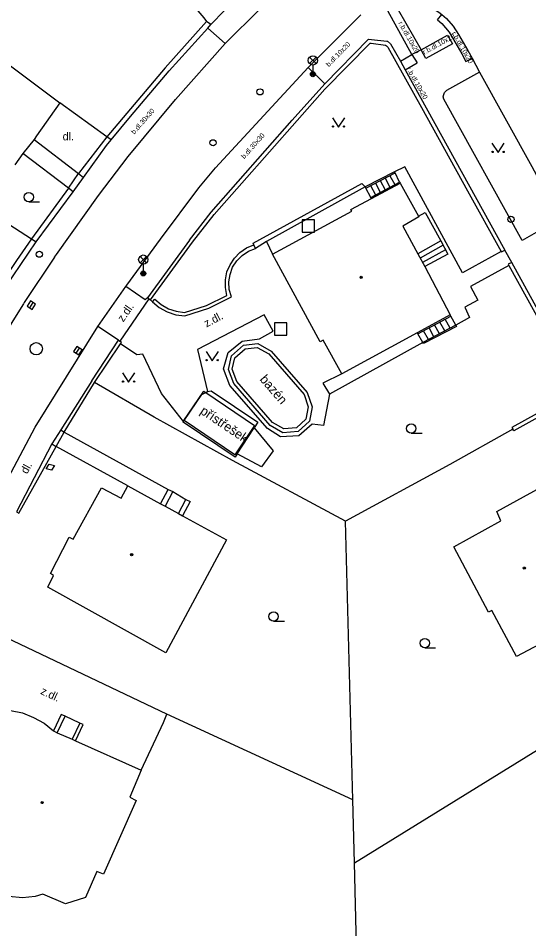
# Model space of a CAD drawing. Extents: x -600309 to -598967, y -1161267 to -1160292.
# Drawn here: x -599938 to -599896.6, y -1160562.7 to -1160488.8 of the extents above; entities that cross this region are included whole.
import ezdxf

# ---------------------------------------------------------------- set-up
doc = ezdxf.new("R2010")
doc.units = 0
for name, color, linetype in [('Level 10', 7, 'Continuous'), ('Level 11', 7, 'Continuous'), ('Level 24', 7, 'Continuous'), ('Level 26', 7, 'Continuous'), ('Level 27', 7, 'Continuous'), ('Level 28', 7, 'Continuous'), ('Level 31', 7, 'Continuous'), ('Level 33', 7, 'Continuous'), ('Level 36', 7, 'Continuous'), ('Level 39', 7, 'Continuous'), ('Level 40', 7, 'Continuous'), ('Level 42', 7, 'Continuous'), ('Level 5', 7, 'Continuous'), ('Level 51', 7, 'Continuous'), ('Level 6', 7, 'Continuous'), ('Level 7', 7, 'Continuous'), ('Level 8', 7, 'Continuous')]:
    doc.layers.add(name, color=color, linetype=linetype)

msp = doc.modelspace()

# ---------------------------------------------------------------- linework, layer by layer
at = {"layer": 'Level 10'}
for points in [[(-599935.03, -1160508.16), (-599934.89, -1160507.96), (-599931.48, -1160503.15), (-599929.06, -1160499.99), (-599925.22, -1160495.36), (-599921.2, -1160490.82), (-599918.35, -1160488), (-599916.19, -1160485.82), (-599913.18, -1160482.88), (-599912.64, -1160482.36)], [(-599904.54, -1160487.84), (-599903.85, -1160488.27), (-599903.61, -1160488.47), (-599903.24, -1160488.79), (-599902.7, -1160489.4), (-599902.26, -1160490.08)], [(-599929.17, -1160510.45), (-599926.44, -1160506.7), (-599923.32, -1160502.53), (-599921.97, -1160500.92), (-599914.47, -1160492.76), (-599913.88, -1160492.17), (-599910.18, -1160488.49)], [(-599902.26, -1160490.08), (-599901.51, -1160491.38), (-599901.17, -1160492.01), (-599900.56, -1160493.13)], [(-599900.56, -1160493.13), (-599896.33, -1160500.81), (-599894.52, -1160504.12)], [(-599935.03, -1160508.16), (-599937.49, -1160511.84), (-599937.56, -1160511.95), (-599938.03, -1160512.7), (-599939.64, -1160515.26), (-599941.75, -1160518.63), (-599946.15, -1160526.95), (-599959.57, -1160556.4699), (-599964.29, -1160566.81), (-599966.33, -1160571.27), (-599969.39, -1160577.98), (-599972.6, -1160585.01), (-599977.2, -1160595.1)], [(-599931.52, -1160513.79), (-599929.25, -1160510.56), (-599929.17, -1160510.45)], [(-599971.83, -1160598.12), (-599968.08, -1160589.86), (-599959.85, -1160571.72), (-599958.48, -1160568.71), (-599957.16, -1160565.81), (-599954.26, -1160559.42), (-599946.03, -1160541.39), (-599945.51, -1160540.25), (-599944.42, -1160537.85), (-599944.31, -1160537.6), (-599940.51, -1160529.28), (-599936.62, -1160521.9699), (-599931.52, -1160513.79)]]:
    msp.add_lwpolyline(points, dxfattribs=at)
at = {"layer": 'Level 11'}
for points in [[(-599925.56, -1160485.64), (-599922.94, -1160488.74), (-599922.7, -1160489.03)], [(-599907.16, -1160488.08), (-599905.3, -1160491.34), (-599906.04, -1160491.72), (-599908, -1160488.16)], [(-599922.36, -1160489.28), (-599922.7, -1160489.03)], [(-599903.96, -1160488.9), (-599903.61, -1160488.47)], [(-599903.96, -1160488.9), (-599903.62, -1160489.2), (-599903.31, -1160489.53), (-599903.03, -1160489.89)], [(-599922.59, -1160489.57), (-599921.2, -1160490.82)], [(-599903.03, -1160489.89), (-599902.75, -1160490.36), (-599902, -1160491.65), (-599901.66, -1160492.28)], [(-599902.75, -1160490.83), (-599904.91, -1160492.03), (-599905.3, -1160491.34), (-599903.15, -1160490.15)], [(-599903.15, -1160490.15), (-599902.75, -1160490.83)], [(-599906.97, -1160492.25), (-599906.04, -1160491.72)], [(-599906.04, -1160491.72), (-599905.61, -1160492.38)], [(-599901.66, -1160492.28), (-599901.17, -1160492.01)], [(-599914.47, -1160492.76), (-599913.1, -1160494.09)], [(-599906.59, -1160492.94), (-599905.61, -1160492.38)], [(-599900.56, -1160493.13), (-599903.25, -1160494.64)], [(-599903.46, -1160495.34), (-599903.5, -1160495.15), (-599903.47, -1160494.95), (-599903.39, -1160494.78), (-599903.25, -1160494.64)], [(-599895.97, -1160506.17), (-599897.09, -1160506.81), (-599903.46, -1160495.34)], [(-599936.7, -1160498.62), (-599933.09, -1160501.36)], [(-599933.92, -1160502.56), (-599937.61, -1160499.76)], [(-599898.8, -1160507.71), (-599901.93, -1160509.45), (-599906.62, -1160500.82), (-599907.45, -1160501.23)], [(-599933.92, -1160502.56), (-599933.09, -1160501.36)], [(-599907.45, -1160501.23), (-599909.83, -1160502.46)], [(-599909.78, -1160502.55), (-599907.4, -1160501.32)], [(-599908.23, -1160501.75), (-599907.83, -1160502.48)], [(-599907.84, -1160501.55), (-599907.44, -1160502.27)], [(-599907.4, -1160501.32), (-599907.45, -1160501.23)], [(-599907.06, -1160502.07), (-599907.4, -1160501.32)], [(-599918.86, -1160507.1599), (-599918.93, -1160507.02), (-599910.11, -1160502.18), (-599909.83, -1160502.46)], [(-599909.83, -1160502.46), (-599917.84, -1160506.9)], [(-599909.83, -1160502.46), (-599909.78, -1160502.55)], [(-599909.4, -1160502.35), (-599909, -1160503.11)], [(-599909.38, -1160503.31), (-599907.06, -1160502.07)], [(-599909.01, -1160502.15), (-599908.61, -1160502.9)], [(-599908.62, -1160501.95), (-599908.2199, -1160502.69)], [(-599907.06, -1160502.07), (-599907.01, -1160502.1599)], [(-599909.38, -1160503.31), (-599909.78, -1160502.55)], [(-599909.33, -1160503.4), (-599909.38, -1160503.31)], [(-599905.51, -1160504.85), (-599904.98, -1160504.55), (-599903.69, -1160506.85)], [(-599917.84, -1160506.9), (-599918.73, -1160507.45)], [(-599917.84, -1160506.9), (-599917.35, -1160507.9099)], [(-599903.69, -1160506.85), (-599905.56, -1160507.89)], [(-599903.69, -1160506.85), (-599903.13, -1160507.9099), (-599905.01, -1160508.93)], [(-599921.05, -1160511.27), (-599921.17, -1160510.64), (-599921.17, -1160510), (-599921.05, -1160509.37), (-599920.8, -1160508.78), (-599920.45, -1160508.24), (-599920, -1160507.78), (-599919.4699, -1160507.42), (-599918.86, -1160507.1599)], [(-599920.69, -1160511.4), (-599920.86, -1160510.8), (-599920.89, -1160510.18), (-599920.8, -1160509.57), (-599920.59, -1160508.99), (-599920.26, -1160508.4699), (-599919.82, -1160508.02), (-599919.31, -1160507.68), (-599918.73, -1160507.45)], [(-599918.73, -1160507.45), (-599918.86, -1160507.1599)], [(-599903.5, -1160507.2), (-599905.37, -1160508.24)], [(-599903.32, -1160507.56), (-599905.18, -1160508.6)], [(-599898.19, -1160508.83), (-599901.29, -1160510.56), (-599900.71, -1160511.6599), (-599901.75, -1160512.24), (-599901.38, -1160513.08), (-599902.49, -1160513.7)], [(-599927.5, -1160511.46), (-599927.69, -1160511.64), (-599929.25, -1160510.56)], [(-599926.89, -1160511.58), (-599926.38, -1160512.02), (-599925.79, -1160512.35), (-599925.1599, -1160512.56), (-599924.49, -1160512.65), (-599922.7199, -1160512.08), (-599921.05, -1160511.27)], [(-599927.1, -1160511.79), (-599927.25, -1160511.63)], [(-599927.1, -1160511.79), (-599926.54, -1160512.26), (-599925.89, -1160512.62), (-599925.19, -1160512.85), (-599924.46, -1160512.94), (-599922.52, -1160512.31), (-599920.69, -1160511.4)], [(-599927.1, -1160511.79), (-599926.89, -1160511.58)], [(-599912.7199, -1160519.28), (-599913.23, -1160521.85), (-599914.13, -1160521.74), (-599915.21, -1160522.69), (-599916.7199, -1160522.77), (-599917.77, -1160522.09), (-599920.81, -1160518.6), (-599921.34, -1160517.23), (-599920.95, -1160515.9), (-599919.83, -1160514.99), (-599918.4099, -1160514.8), (-599917.31, -1160514.19), (-599918.02, -1160512.84), (-599923.43, -1160515.6599), (-599922.62, -1160519.09)], [(-599902.9, -1160512.96), (-599902.95, -1160512.86)], [(-599905.56, -1160514.4), (-599902.9, -1160512.96)], [(-599903.37, -1160514.1599), (-599903.78, -1160513.44)], [(-599902.93, -1160513.93), (-599903.34, -1160513.2)], [(-599902.49, -1160513.7), (-599902.9, -1160512.96)], [(-599929.85, -1160514.92), (-599931.52, -1160513.79)], [(-599905.61, -1160514.31), (-599905.56, -1160514.4)], [(-599902.49, -1160513.7), (-599905.1599, -1160515.1)], [(-599902.49, -1160513.7), (-599902.44, -1160513.79), (-599905.11, -1160515.19), (-599905.1599, -1160515.1)], [(-599904.7, -1160514.86), (-599905.1, -1160514.15)], [(-599904.26, -1160514.63), (-599904.6599, -1160513.9099)], [(-599903.81, -1160514.39), (-599904.2199, -1160513.67)], [(-599905.1599, -1160515.1), (-599905.56, -1160514.4)], [(-599924.57, -1160521.51), (-599926.36, -1160519.25), (-599927.88, -1160516.05), (-599928.35, -1160516.09), (-599929.68, -1160515.21)], [(-599917.46, -1160515.79), (-599914.54, -1160519.1599), (-599914.14, -1160520.31), (-599914.36, -1160521.48), (-599915.27, -1160522.32), (-599916.51, -1160522.42), (-599917.54, -1160521.84), (-599920.5, -1160518.42), (-599920.93, -1160517.3), (-599920.69, -1160516.17), (-599919.71, -1160515.31), (-599918.54, -1160515.18), (-599917.46, -1160515.79)], [(-599917.65, -1160516.03), (-599914.8, -1160519.31), (-599914.45, -1160520.33), (-599914.64, -1160521.33), (-599915.4, -1160522.03), (-599916.44, -1160522.11), (-599917.35, -1160521.6), (-599920.24, -1160518.26), (-599920.62, -1160517.27), (-599920.42, -1160516.33), (-599919.58, -1160515.6), (-599918.6, -1160515.49), (-599917.65, -1160516.03)], [(-599905.1599, -1160515.1), (-599912.7199, -1160519.28)], [(-599911.74, -1160517.63), (-599913.27, -1160518.39), (-599912.7199, -1160519.28)], [(-599924.53, -1160521.44), (-599923.09, -1160519.32), (-599922.76, -1160519.1599)], [(-599922.76, -1160519.1599), (-599922.62, -1160519.09)], [(-599922.62, -1160519.09), (-599922.34, -1160519.01), (-599918.55, -1160521.56), (-599918.84, -1160522.03)], [(-599920.21, -1160524.13), (-599920.38, -1160524.4099), (-599924.61, -1160521.57), (-599924.57, -1160521.51)], [(-599924.57, -1160521.51), (-599924.53, -1160521.44)], [(-599934.92, -1160523.54), (-599934.26, -1160522.37)], [(-599934.26, -1160522.37), (-599925.83, -1160527.03)], [(-599918.84, -1160522.03), (-599917.29, -1160523.9), (-599918.26, -1160525.2), (-599920.21, -1160524.13)], [(-599920.21, -1160524.13), (-599918.84, -1160522.03)], [(-599929.1, -1160526.74), (-599934.92, -1160523.54)], [(-599926.43, -1160528.2), (-599925.83, -1160527.03)], [(-599925.45, -1160527.21), (-599926.06, -1160528.4)], [(-599925.83, -1160527.03), (-599925.45, -1160527.21)], [(-599925.45, -1160527.21), (-599924.38, -1160527.84)], [(-599924.98, -1160528.99), (-599924.38, -1160527.84)], [(-599924.04, -1160528), (-599924.6599, -1160529.17)], [(-599924.38, -1160527.84), (-599924.04, -1160528)], [(-599934.19, -1160545.45), (-599934.51, -1160545.3), (-599935.13, -1160546.64)], [(-599926.2, -1160545.9699), (-599925.94, -1160545.28)], [(-599934.83, -1160546.79), (-599934.19, -1160545.45)], [(-599933, -1160546), (-599934.19, -1160545.45)], [(-599933, -1160546), (-599933.6, -1160547.32)], [(-599933.34, -1160547.46), (-599932.73, -1160546.12), (-599933, -1160546)], [(-599928.01, -1160549.84), (-599926.2, -1160545.9699)]]:
    msp.add_lwpolyline(points, dxfattribs=at)
at = {"layer": 'Level 24'}
msp.add_lwpolyline([(-599935.72, -1160525.35), (-599935.47, -1160524.97), (-599935.04, -1160525.09), (-599935.29, -1160525.47), (-599935.72, -1160525.35)], dxfattribs=at)
at = {"layer": 'Level 26'}
for points in [[(-599914.94, -1160506.14), (-599913.94, -1160506.14), (-599913.94, -1160505.14), (-599914.94, -1160505.14)], [(-599917.2, -1160514.49), (-599916.2, -1160514.49), (-599916.2, -1160513.49), (-599917.2, -1160513.49)]]:
    msp.add_lwpolyline(points, close=True, dxfattribs=at)
at = {"layer": 'Level 27'}
for p, q in [((-599937.054, -1160512.281), (-599936.786, -1160511.859)), ((-599933.2867, -1160515.9693), (-599933.0133, -1160515.5507))]:
    msp.add_line(p, q, dxfattribs=at)
for points in [[(-599936.843, -1160512.4151), (-599936.5749, -1160511.993), (-599936.997, -1160511.7249), (-599937.2651, -1160512.147)], [(-599933.0773, -1160516.106), (-599932.804, -1160515.6873), (-599933.2227, -1160515.414), (-599933.496, -1160515.8327)]]:
    msp.add_lwpolyline(points, close=True, dxfattribs=at)
msp.add_circle((-599936.52, -1160515.6), 0.5, dxfattribs=at)
at = {"layer": 'Level 28'}
for centre in [(-599918.37, -1160494.74), (-599922.18, -1160498.88), (-599936.27, -1160507.93)]:
    msp.add_circle(centre, 0.25, dxfattribs=at)
at = {"layer": 'Level 31'}
msp.add_circle((-599898.01, -1160505.1), 0.25, dxfattribs=at)
at = {"layer": 'Level 33'}
for p, q in [((-599914.345, -1160492.45), (-599913.815, -1160491.92)), ((-599914.345, -1160491.92), (-599913.815, -1160492.45)), ((-599914.08, -1160492.56), (-599914.08, -1160493.31)), ((-599928.105, -1160508.63), (-599927.575, -1160508.1)), ((-599928.105, -1160508.1), (-599927.575, -1160508.63)), ((-599927.84, -1160508.74), (-599927.84, -1160509.49))]:
    msp.add_line(p, q, dxfattribs=at)
for centre, radius in [((-599914.08, -1160492.185), 0.375), ((-599914.08, -1160493.31), 0.2), ((-599914.08, -1160493.31), 0.1445), ((-599914.08, -1160493.31), 0.0876), ((-599927.84, -1160508.365), 0.375), ((-599927.84, -1160509.49), 0.2), ((-599927.84, -1160509.49), 0.1445), ((-599927.84, -1160509.49), 0.0876)]:
    msp.add_circle(centre, radius, dxfattribs=at)
at = {"layer": 'Level 36'}
for p, q in [((-599937.13, -1160503.665), (-599936.255, -1160503.665)), ((-599906.1, -1160522.455), (-599905.225, -1160522.455)), ((-599917.27, -1160537.725), (-599916.395, -1160537.725)), ((-599905, -1160539.885), (-599904.125, -1160539.885))]:
    msp.add_line(p, q, dxfattribs=at)
for points in [[(-599912.5, -1160496.85), (-599912, -1160497.6), (-599911.5, -1160496.85)], [(-599899.55, -1160498.92), (-599899.05, -1160499.67), (-599898.55, -1160498.92)], [(-599922.75, -1160515.83), (-599922.25, -1160516.58), (-599921.75, -1160515.83)], [(-599929.53, -1160517.57), (-599929.03, -1160518.32), (-599928.53, -1160517.57)]]:
    msp.add_lwpolyline(points, dxfattribs=at)
for centre, radius in [((-599912.4502, -1160497.5498), 0.05), ((-599911.5508, -1160497.5498), 0.05), ((-599899.5002, -1160499.6198), 0.05), ((-599898.6008, -1160499.6198), 0.05), ((-599937.1301, -1160503.2899), 0.375), ((-599922.7002, -1160516.5298), 0.05), ((-599921.8008, -1160516.5298), 0.05), ((-599929.4802, -1160518.2698), 0.05), ((-599928.5808, -1160518.2698), 0.05), ((-599906.1001, -1160522.0799), 0.375), ((-599917.2701, -1160537.3499), 0.375), ((-599905.0001, -1160539.5099), 0.375)]:
    msp.add_circle(centre, radius, dxfattribs=at)
at = {"layer": 'Level 39'}
for centre, radius in [((-599910.1599, -1160509.8), 0.09), ((-599910.1599, -1160509.8), 0.0398), ((-599928.79, -1160532.33), 0.09), ((-599928.79, -1160532.33), 0.0398), ((-599896.93, -1160533.42), 0.09), ((-599896.93, -1160533.42), 0.0398), ((-599936.04, -1160552.46), 0.09), ((-599936.04, -1160552.46), 0.0398)]:
    msp.add_circle(centre, radius, dxfattribs=at)
at = {"layer": 'Level 5'}
for points in [[(-599943.04, -1160489.33), (-599934.62, -1160495.63)], [(-599934.62, -1160495.63), (-599936.51, -1160498.3)], [(-599936.7, -1160498.62), (-599937.61, -1160499.76)], [(-599936.51, -1160498.3), (-599936.7, -1160498.62)], [(-599937.61, -1160499.76), (-599938.27, -1160500.67)], [(-599909.33, -1160503.4), (-599907.01, -1160502.1599)], [(-599907.01, -1160502.1599), (-599905.51, -1160504.85)], [(-599911, -1160504.29), (-599909.33, -1160503.4)], [(-599917.35, -1160507.9099), (-599910.92, -1160504.44)], [(-599910.92, -1160504.44), (-599911, -1160504.29)], [(-599905.48, -1160504.9), (-599906.78, -1160505.64)], [(-599905.51, -1160504.85), (-599905.48, -1160504.9)], [(-599906.78, -1160505.64), (-599905.56, -1160507.89)], [(-599913.5, -1160515.05), (-599917.35, -1160507.9099)], [(-599905.56, -1160507.89), (-599905.01, -1160508.93)], [(-599905.01, -1160508.93), (-599902.95, -1160512.86)], [(-599902.95, -1160512.86), (-599905.61, -1160514.31)], [(-599905.61, -1160514.31), (-599911.74, -1160517.63)], [(-599913.24, -1160514.9099), (-599913.5, -1160515.05)], [(-599911.74, -1160517.63), (-599913.24, -1160514.9099)], [(-599899.17, -1160528.81), (-599893.99, -1160525.99)], [(-599933.54, -1160531.06), (-599931.24, -1160526.9)], [(-599931.24, -1160526.9), (-599929.63, -1160527.73)], [(-599929.63, -1160527.73), (-599929.1, -1160526.74)], [(-599929.1, -1160526.74), (-599926.43, -1160528.2)], [(-599926.43, -1160528.2), (-599926.06, -1160528.4)], [(-599926.06, -1160528.4), (-599924.98, -1160528.99)], [(-599924.98, -1160528.99), (-599924.6599, -1160529.17)], [(-599898.84, -1160529.57), (-599899.17, -1160528.81)], [(-599924.6599, -1160529.17), (-599921.09, -1160531.13)], [(-599902.65, -1160531.7), (-599898.84, -1160529.57)], [(-599935.38, -1160533.86), (-599933.86, -1160530.92)], [(-599933.86, -1160530.92), (-599933.54, -1160531.06)], [(-599921.09, -1160531.13), (-599926.02, -1160540.29)], [(-599899.84, -1160537.01), (-599902.65, -1160531.7)], [(-599935.59, -1160534.98), (-599935.13, -1160534.01)], [(-599935.13, -1160534.01), (-599935.38, -1160533.86)], [(-599926.02, -1160540.29), (-599935.59, -1160534.98)], [(-599899.56, -1160536.85), (-599899.84, -1160537.01)], [(-599897.57, -1160540.6), (-599899.56, -1160536.85)], [(-599890.2199, -1160536.71), (-599897.57, -1160540.6)], [(-599938.61, -1160544.98), (-599937.65, -1160545.18)], [(-599937.65, -1160545.18), (-599936.74, -1160545.54)], [(-599936.74, -1160545.54), (-599935.89, -1160546.02)], [(-599935.89, -1160546.02), (-599935.13, -1160546.64)], [(-599935.13, -1160546.64), (-599934.83, -1160546.79)], [(-599934.83, -1160546.79), (-599933.6, -1160547.32)], [(-599933.6, -1160547.32), (-599933.34, -1160547.46)], [(-599933.34, -1160547.46), (-599928.01, -1160549.84)], [(-599928.01, -1160549.84), (-599928.92, -1160552.03)], [(-599928.92, -1160552.03), (-599928.43, -1160552.28)], [(-599928.43, -1160552.28), (-599931.08, -1160558.27)], [(-599931.6, -1160558.06), (-599932.52, -1160560.1599)], [(-599931.08, -1160558.27), (-599931.6, -1160558.06)], [(-599937.63, -1160560.21), (-599938.76, -1160560.09)], [(-599936.6, -1160560.08), (-599937.63, -1160560.21)], [(-599935.98, -1160559.9), (-599936.6, -1160560.08)], [(-599934.14, -1160560.69), (-599935.98, -1160559.9)], [(-599932.52, -1160560.1599), (-599934.14, -1160560.69)]]:
    msp.add_lwpolyline(points, dxfattribs=at)
at = {"layer": 'Level 51'}
for points in [[(-599910.84, -1160552.24), (-599911.43, -1160529.61)], [(-599910.84, -1160552.24), (-599925.94, -1160545.28)], [(-599910.7, -1160557.35), (-599895.86, -1160548.19)], [(-599910.7, -1160557.35), (-599910.84, -1160552.24)], [(-599910.35, -1160572.03), (-599910.7, -1160557.35)]]:
    msp.add_lwpolyline(points, dxfattribs=at)
at = {"layer": 'Level 6'}
for points in [[(-599924.56, -1160521.42), (-599922.94, -1160519.04)], [(-599922.94, -1160519.04), (-599922.76, -1160519.1599)], [(-599922.76, -1160519.1599), (-599918.81, -1160521.85)], [(-599924.53, -1160521.44), (-599924.56, -1160521.42)], [(-599920.4099, -1160524.2199), (-599924.53, -1160521.44)], [(-599918.81, -1160521.85), (-599920.4099, -1160524.2199)]]:
    msp.add_lwpolyline(points, dxfattribs=at)
at = {"layer": 'Level 7'}
for points in [[(-599922.7, -1160489.03), (-599926.07, -1160492.79), (-599930.81, -1160498.39)], [(-599930.82, -1160499.1), (-599930.45, -1160498.65), (-599928.88, -1160496.75), (-599925.74, -1160493.04), (-599922.59, -1160489.57), (-599922.36, -1160489.28)], [(-599924.1, -1160506.78), (-599922.33, -1160504.51), (-599915.76, -1160497.03), (-599913.1, -1160494.09), (-599909.56, -1160490.45)], [(-599909.56, -1160490.45), (-599909.32, -1160490.48), (-599908.07, -1160490.62), (-599908.04, -1160490.62), (-599907.78, -1160490.85), (-599906.97, -1160492.25), (-599906.59, -1160492.94), (-599898.51, -1160507.59)], [(-599927.25, -1160511.63), (-599923.86, -1160506.96), (-599922.1, -1160504.71), (-599913.1, -1160494.52), (-599909.42, -1160490.79), (-599909.36, -1160490.8)], [(-599909.36, -1160490.8), (-599908.19, -1160490.94), (-599908.12, -1160491)], [(-599908.12, -1160491), (-599907.99, -1160491.1), (-599905.28, -1160496.02), (-599901.53, -1160502.77), (-599898.8, -1160507.71)], [(-599930.81, -1160498.39), (-599934.62, -1160495.63)], [(-599930.81, -1160498.39), (-599933.09, -1160501.36)], [(-599930.45, -1160498.65), (-599930.81, -1160498.39)], [(-599932.7, -1160501.7), (-599930.82, -1160499.1)], [(-599933.09, -1160501.36), (-599932.7, -1160501.7)], [(-599933.92, -1160502.56), (-599936.92, -1160506.67)], [(-599936.52, -1160506.92), (-599933.54, -1160502.85)], [(-599933.54, -1160502.85), (-599933.92, -1160502.56)], [(-599940.69, -1160504.23), (-599936.92, -1160506.67)], [(-599942.2, -1160515.67), (-599941.23, -1160514.13), (-599939.69, -1160511.68), (-599939.18, -1160510.86), (-599939.02, -1160510.61), (-599936.52, -1160506.92)], [(-599936.92, -1160506.67), (-599938.13, -1160508.44), (-599938.35, -1160508.77), (-599939.43, -1160510.36)], [(-599936.92, -1160506.67), (-599936.52, -1160506.92)], [(-599924.1, -1160506.78), (-599927.5, -1160511.46)], [(-599898.8, -1160507.71), (-599898.79, -1160507.73), (-599898.51, -1160507.59)], [(-599897.95, -1160508.59), (-599898.24, -1160508.73)], [(-599898.24, -1160508.73), (-599898.19, -1160508.83)], [(-599898.19, -1160508.83), (-599892.56, -1160519.03), (-599897.94, -1160522.01), (-599897.87, -1160522.14)], [(-599892.17, -1160519.14), (-599892.22, -1160519.05), (-599897.95, -1160508.59)], [(-599927.38, -1160511.54), (-599927.5, -1160511.46)], [(-599927.38, -1160511.54), (-599927.25, -1160511.63)], [(-599932.02, -1160518.2), (-599929.85, -1160514.92)], [(-599929.85, -1160514.92), (-599929.73, -1160515)], [(-599929.68, -1160515.21), (-599929.6, -1160515.09), (-599929.73, -1160515)], [(-599931.8, -1160518.34), (-599929.68, -1160515.21)], [(-599932.02, -1160518.2), (-599934.53, -1160522.2)], [(-599934.26, -1160522.37), (-599931.8, -1160518.34)], [(-599911.43, -1160529.61), (-599920.6, -1160524.68), (-599926.9699, -1160521.17), (-599931.8, -1160518.34)], [(-599892.61, -1160519.4), (-599897.79, -1160522.27), (-599897.87, -1160522.14)], [(-599934.53, -1160522.2), (-599934.26, -1160522.37)], [(-599897.87, -1160522.14), (-599902.96, -1160525), (-599911.43, -1160529.61)], [(-599935.25, -1160523.34), (-599938.12, -1160528.86), (-599937.94, -1160528.96)], [(-599937.94, -1160528.96), (-599934.92, -1160523.54)], [(-599935.25, -1160523.34), (-599934.92, -1160523.54)], [(-599925.94, -1160545.28), (-599940.68, -1160538.28)]]:
    msp.add_lwpolyline(points, dxfattribs=at)
at = {"layer": 'Level 8'}
for points in [[(-599922.36, -1160489.28), (-599920.14, -1160486.97)], [(-599933.54, -1160502.85), (-599932.7, -1160501.7)], [(-599897.95, -1160508.59), (-599898.51, -1160507.59)], [(-599927.38, -1160511.54), (-599929.73, -1160515)], [(-599934.53, -1160522.2), (-599935.25, -1160523.34)]]:
    msp.add_lwpolyline(points, dxfattribs=at)

# ---------------------------------------------------------------- texts
at = {"layer": 'Level 40'}
for s, height, rotation, p in [('r.b.dl.10x20', 0.400002, 299.707011, (-599907.17, -1160489.17)), ('r.b.dl.10x20', 0.400002, 299.707011, (-599902.83, -1160489.98)), ('r.b.dl.10x20', 0.400002, 29, (-599905.04, -1160491.73)), ('b.dl.10x20', 0.4, 45.797939, (-599912.78, -1160492.74)), ('r.b.dl.10x20', 0.400002, 299.707011, (-599906.51, -1160492.88)), ('b.dl.30x30', 0.4, 48.705797, (-599928.57, -1160498.22)), ('b.dl.30x30', 0.4, 48.705797, (-599919.64, -1160500.22)), ('z.dl.', 0.65, 55.155708, (-599929.47, -1160513.48)), ('z.dl.', 0.65, 27.531092, (-599922.71, -1160513.88)), ('dl.', 0.65, 61.426114, (-599937.27, -1160525.82)), ('z.dl.', 0.65, 335, (-599936.23, -1160543.62))]:
    msp.add_text(s, height=height, rotation=rotation, dxfattribs=at).set_placement(p)
msp.add_text('dl.', height=0.65, dxfattribs=at).set_placement((-599934.38, -1160498.68))
at = {"layer": 'Level 42'}
for s, rotation, p in [('bazén', 310.917039, (-599918.44, -1160518.12)), ('přístřešek', 326.066419, (-599923.29, -1160520.82))]:
    msp.add_text(s, height=0.75, rotation=rotation, dxfattribs=at).set_placement(p)

doc.saveas('drawing.dxf')
